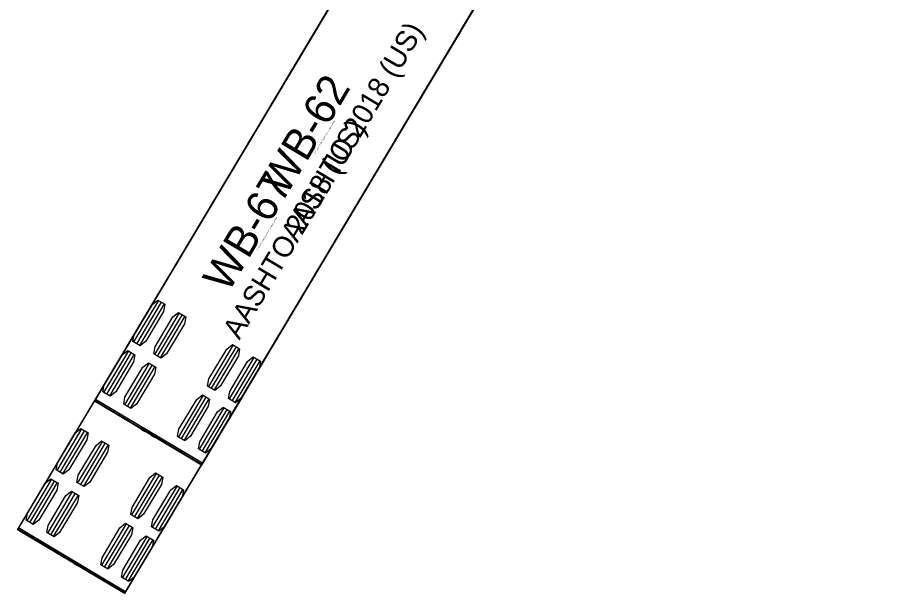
# Model space of a CAD drawing. Extents: x 973688 to 979179, y 703586 to 707602.
# Drawn here: x 978497.5 to 978557.1, y 703814.4 to 703853.8 of the extents above; entities that cross this region are included whole.
import ezdxf

# ---------------------------------------------------------------- set-up
doc = ezdxf.new("R2010")
doc.units = 0
doc.layers.add('Radius Check', color=7, linetype='Continuous')

msp = doc.modelspace()

# ---------------------------------------------------------------- linework, layer by layer
at = {"layer": 'Radius Check'}
for p, q in [((978507.137, 703834.449), (978505.447, 703831.615)), ((978507.334, 703834.332), (978505.644, 703831.498)), ((978507.531, 703834.215), (978505.841, 703831.38)), ((978508.554, 703833.604), (978506.864, 703830.77)), ((978508.751, 703833.487), (978507.061, 703830.653)), ((978508.948, 703833.37), (978507.258, 703830.535)), ((978512.233, 703831.411), (978510.543, 703828.576)), ((978512.43, 703831.293), (978510.74, 703828.459)), ((978512.627, 703831.176), (978510.937, 703828.342)), ((978505.088, 703831.014), (978503.398, 703828.179)), ((978505.285, 703830.896), (978503.595, 703828.062)), ((978505.482, 703830.779), (978503.792, 703827.945)), ((978506.506, 703830.169), (978504.816, 703827.334)), ((978506.702, 703830.051), (978505.012, 703827.217)), ((978513.65, 703830.566), (978511.96, 703827.731)), ((978513.847, 703830.448), (978512.157, 703827.614)), ((978514.044, 703830.331), (978512.354, 703827.497)), ((978506.899, 703829.934), (978505.209, 703827.1)), ((978510.139, 703823.335), (978502.838, 703827.688)), ((978510.185, 703827.975), (978508.494, 703825.141)), ((978510.381, 703827.858), (978508.691, 703825.023)), ((978510.578, 703827.74), (978508.888, 703824.906)), ((978511.602, 703827.13), (978509.912, 703824.296)), ((978511.799, 703827.013), (978510.109, 703824.178)), ((978511.995, 703826.895), (978510.305, 703824.061)), ((978501.896, 703825.687), (978500.205, 703822.854)), ((978502.093, 703825.57), (978500.401, 703822.736)), ((978502.29, 703825.452), (978500.598, 703822.619)), ((978506.225, 703825.587), (978505.996, 703825.723)), ((978506.453, 703825.451), (978506.489, 703825.511)), ((978506.909, 703825.179), (978506.681, 703825.315)), ((978503.313, 703824.841), (978501.621, 703822.008)), ((978503.51, 703824.724), (978501.818, 703821.891)), ((978503.706, 703824.607), (978502.015, 703821.773)), ((978499.846, 703822.253), (978498.154, 703819.419)), ((978506.991, 703822.646), (978505.299, 703819.812)), ((978507.187, 703822.528), (978505.496, 703819.695)), ((978507.384, 703822.411), (978505.693, 703819.577)), ((978500.043, 703822.135), (978498.351, 703819.302)), ((978500.239, 703822.018), (978498.548, 703819.184)), ((978508.407, 703821.8), (978506.716, 703818.967)), ((978508.604, 703821.682), (978506.913, 703818.849)), ((978501.262, 703821.407), (978499.571, 703818.574)), ((978501.459, 703821.29), (978499.768, 703818.456)), ((978501.656, 703821.172), (978499.964, 703818.339)), ((978508.801, 703821.565), (978507.109, 703818.732)), ((978504.892, 703814.571), (978497.594, 703818.928)), ((978504.94, 703819.211), (978503.249, 703816.378)), ((978505.137, 703819.094), (978503.445, 703816.26)), ((978505.334, 703818.976), (978503.642, 703816.143)), ((978506.357, 703818.365), (978504.665, 703815.532)), ((978506.554, 703818.248), (978504.862, 703815.415)), ((978506.75, 703818.131), (978505.059, 703815.297)), ((978500.979, 703816.825), (978500.751, 703816.961)), ((978501.207, 703816.689), (978501.243, 703816.75)), ((978501.663, 703816.417), (978501.435, 703816.553))]:
    msp.add_line(p, q, dxfattribs=at)
for points in [[(978497.587, 703818.916), (978548.628, 703904.408)], [(978502.826, 703827.667), (978544.417, 703897.42)], [(978557.142, 703894.906), (978555.921, 703893.818), (978554.693, 703892.652), (978553.448, 703891.396), (978552.204, 703890.065), (978550.962, 703888.659), (978549.723, 703887.18), (978548.487, 703885.63), (978547.256, 703884.011), (978546.028, 703882.327), (978544.8, 703880.575), (978543.565, 703878.75), (978542.317, 703876.852), (978541.053, 703874.878), (978538.466, 703870.72), (978535.814, 703866.347), (978504.82, 703814.45), (978497.522, 703818.807), (978497.587, 703818.916), (978497.587, 703818.916)], [(978555.276, 703894.425), (978554.001, 703893.078), (978552.732, 703891.656), (978551.471, 703890.161), (978550.218, 703888.595), (978548.972, 703886.962), (978547.733, 703885.261), (978546.493, 703883.49), (978545.247, 703881.645), (978543.988, 703879.724), (978542.714, 703877.728), (978540.111, 703873.529), (978537.451, 703869.128), (978510.067, 703823.214), (978502.766, 703827.567), (978502.826, 703827.667), (978502.826, 703827.667)], [(978510.084, 703823.286), (978510.103, 703823.274), (978534.649, 703864.441), (978530.999, 703866.618), (978527.349, 703868.794), (978502.802, 703827.627), (978502.822, 703827.616)], [(978504.837, 703814.522), (978504.855, 703814.511), (978504.892, 703814.571), (978507.797, 703819.437), (978531.989, 703859.957), (978528.339, 703862.135), (978524.69, 703864.314), (978500.499, 703823.794), (978497.595, 703818.928), (978497.558, 703818.867), (978497.577, 703818.856)], [(978502.842, 703827.603), (978502.843, 703827.603), (978505.966, 703825.741), (978505.996, 703825.723), (978505.96, 703825.663), (978505.961, 703825.661), (978506.19, 703825.525)], [(978506.23, 703825.584), (978506.679, 703825.316)], [(978506.643, 703825.255), (978506.872, 703825.119), (978506.873, 703825.118), (978506.909, 703825.178), (978506.94, 703825.16), (978510.062, 703823.298), (978510.063, 703823.298)], [(978497.598, 703818.844), (978497.599, 703818.843), (978500.72, 703816.98), (978500.751, 703816.961), (978500.715, 703816.901), (978500.716, 703816.9), (978500.945, 703816.763)], [(978500.985, 703816.822), (978501.432, 703816.554)], [(978501.397, 703816.494), (978501.626, 703816.357), (978501.627, 703816.357), (978501.663, 703816.417), (978501.694, 703816.398), (978504.815, 703814.535), (978504.816, 703814.534)]]:
    msp.add_lwpolyline(points, dxfattribs=at)
for points in [[(978507.088, 703834.478), (978507.579, 703834.186), (978507.491, 703833.7), (978506.274, 703831.66), (978505.889, 703831.351), (978505.398, 703831.644), (978505.487, 703832.129), (978506.703, 703834.17)], [(978508.505, 703833.633), (978508.997, 703833.341), (978508.908, 703832.855), (978507.691, 703830.815), (978507.307, 703830.506), (978506.815, 703830.799), (978506.904, 703831.284), (978508.121, 703833.325)], [(978512.184, 703831.44), (978512.676, 703831.147), (978512.587, 703830.662), (978511.37, 703828.621), (978510.986, 703828.312), (978510.494, 703828.605), (978510.583, 703829.09), (978511.8, 703831.131)], [(978505.04, 703831.043), (978505.531, 703830.75), (978505.442, 703830.265), (978504.225, 703828.224), (978503.841, 703827.916), (978503.35, 703828.208), (978503.438, 703828.694), (978504.655, 703830.734)], [(978513.601, 703830.595), (978514.093, 703830.302), (978514.004, 703829.817), (978512.787, 703827.776), (978512.403, 703827.467), (978511.911, 703827.76), (978512, 703828.245), (978513.217, 703830.286)], [(978506.457, 703830.198), (978506.948, 703829.905), (978506.859, 703829.42), (978505.643, 703827.379), (978505.258, 703827.07), (978504.767, 703827.363), (978504.855, 703827.849), (978506.072, 703829.889)], [(978510.136, 703828.004), (978510.627, 703827.711), (978510.538, 703827.226), (978509.322, 703825.185), (978508.937, 703824.877), (978508.446, 703825.17), (978508.534, 703825.655), (978509.751, 703827.696)], [(978511.553, 703827.159), (978512.044, 703826.866), (978511.956, 703826.381), (978510.739, 703824.34), (978510.354, 703824.032), (978509.863, 703824.325), (978509.951, 703824.81), (978511.168, 703826.851)], [(978501.847, 703825.716), (978502.339, 703825.423), (978502.25, 703824.938), (978501.032, 703822.898), (978500.647, 703822.59), (978500.156, 703822.883), (978500.245, 703823.368), (978501.463, 703825.408)], [(978503.264, 703824.871), (978503.755, 703824.577), (978503.666, 703824.092), (978502.448, 703822.052), (978502.064, 703821.744), (978501.572, 703822.037), (978501.661, 703822.522), (978502.879, 703824.562)], [(978499.797, 703822.282), (978500.288, 703821.989), (978500.199, 703821.504), (978498.981, 703819.464), (978498.596, 703819.155), (978498.105, 703819.449), (978498.194, 703819.934), (978499.412, 703821.974)], [(978506.942, 703822.675), (978507.433, 703822.382), (978507.344, 703821.897), (978506.126, 703819.857), (978505.741, 703819.548), (978505.25, 703819.841), (978505.339, 703820.326), (978506.557, 703822.367)], [(978508.359, 703821.829), (978508.85, 703821.536), (978508.761, 703821.051), (978507.543, 703819.011), (978507.158, 703818.702), (978506.667, 703818.996), (978506.756, 703819.481), (978507.974, 703821.521)], [(978501.214, 703821.436), (978501.705, 703821.143), (978501.616, 703820.658), (978500.398, 703818.618), (978500.013, 703818.309), (978499.522, 703818.603), (978499.611, 703819.088), (978500.829, 703821.128)], [(978504.891, 703819.24), (978505.383, 703818.947), (978505.294, 703818.462), (978504.076, 703816.422), (978503.691, 703816.114), (978503.2, 703816.407), (978503.289, 703816.892), (978504.507, 703818.932)], [(978506.308, 703818.395), (978506.799, 703818.101), (978506.71, 703817.616), (978505.492, 703815.576), (978505.108, 703815.268), (978504.616, 703815.561), (978504.705, 703816.046), (978505.923, 703818.086)]]:
    msp.add_lwpolyline(points, close=True, dxfattribs=at)
for centre in [(978502.814, 703827.58), (978510.056, 703823.262), (978497.57, 703818.821), (978504.809, 703814.499)]:
    msp.add_circle(centre, 0.0266, dxfattribs=at)
for centre, radius, start, end in [((978502.814, 703827.58), 0.0363, 78.27078, 39.43341), ((978506.208, 703825.555), 0.0352, 58.98151, 241.62091), ((978506.208, 703825.555), 0.0352, 239.20956, 59.79605), ((978506.661, 703825.285), 0.0352, 58.59191, 239.1784), ((978506.661, 703825.285), 0.0354, 243.48551, 55.67098), ((978510.056, 703823.262), 0.0363, 78.95454, 40.11717), ((978497.57, 703818.821), 0.0363, 78.23917, 39.40051), ((978500.963, 703816.794), 0.0353, 62.4979, 240.84755), ((978500.963, 703816.793), 0.0352, 239.18699, 58.1874), ((978501.415, 703816.524), 0.0352, 60.13604, 239.13645), ((978501.415, 703816.524), 0.0354, 243.45326, 55.63872), ((978503.8, 703812.786), 2.022, 59.16172, 59.84548)]:
    msp.add_arc(centre, radius, start, end, dxfattribs=at)

# ---------------------------------------------------------------- texts
for s, height, rotation, p in [('AASHTO 2018 (US)', 1.41667, 59.19398, (978516.613, 703838.328)), ('WB-62', 2.125, 59.19398, (978515.841, 703841.528)), ('AASHTO 2018 (US)', 1.41667, 59.16172, (978512.656, 703831.707)), ('(c) 2020 Transoft Solutions, Inc. All rights reserved.', 0.085, 59.19398, (978517.853, 703844.487)), ('WB-67', 2.125, 59.16172, (978511.886, 703834.908)), ('(c) 2020 Transoft Solutions, Inc. All rights reserved.', 0.085, 59.16172, (978513.899, 703837.866))]:
    msp.add_text(s, height=height, rotation=rotation, dxfattribs=at).set_placement(p)

doc.saveas('drawing.dxf')
